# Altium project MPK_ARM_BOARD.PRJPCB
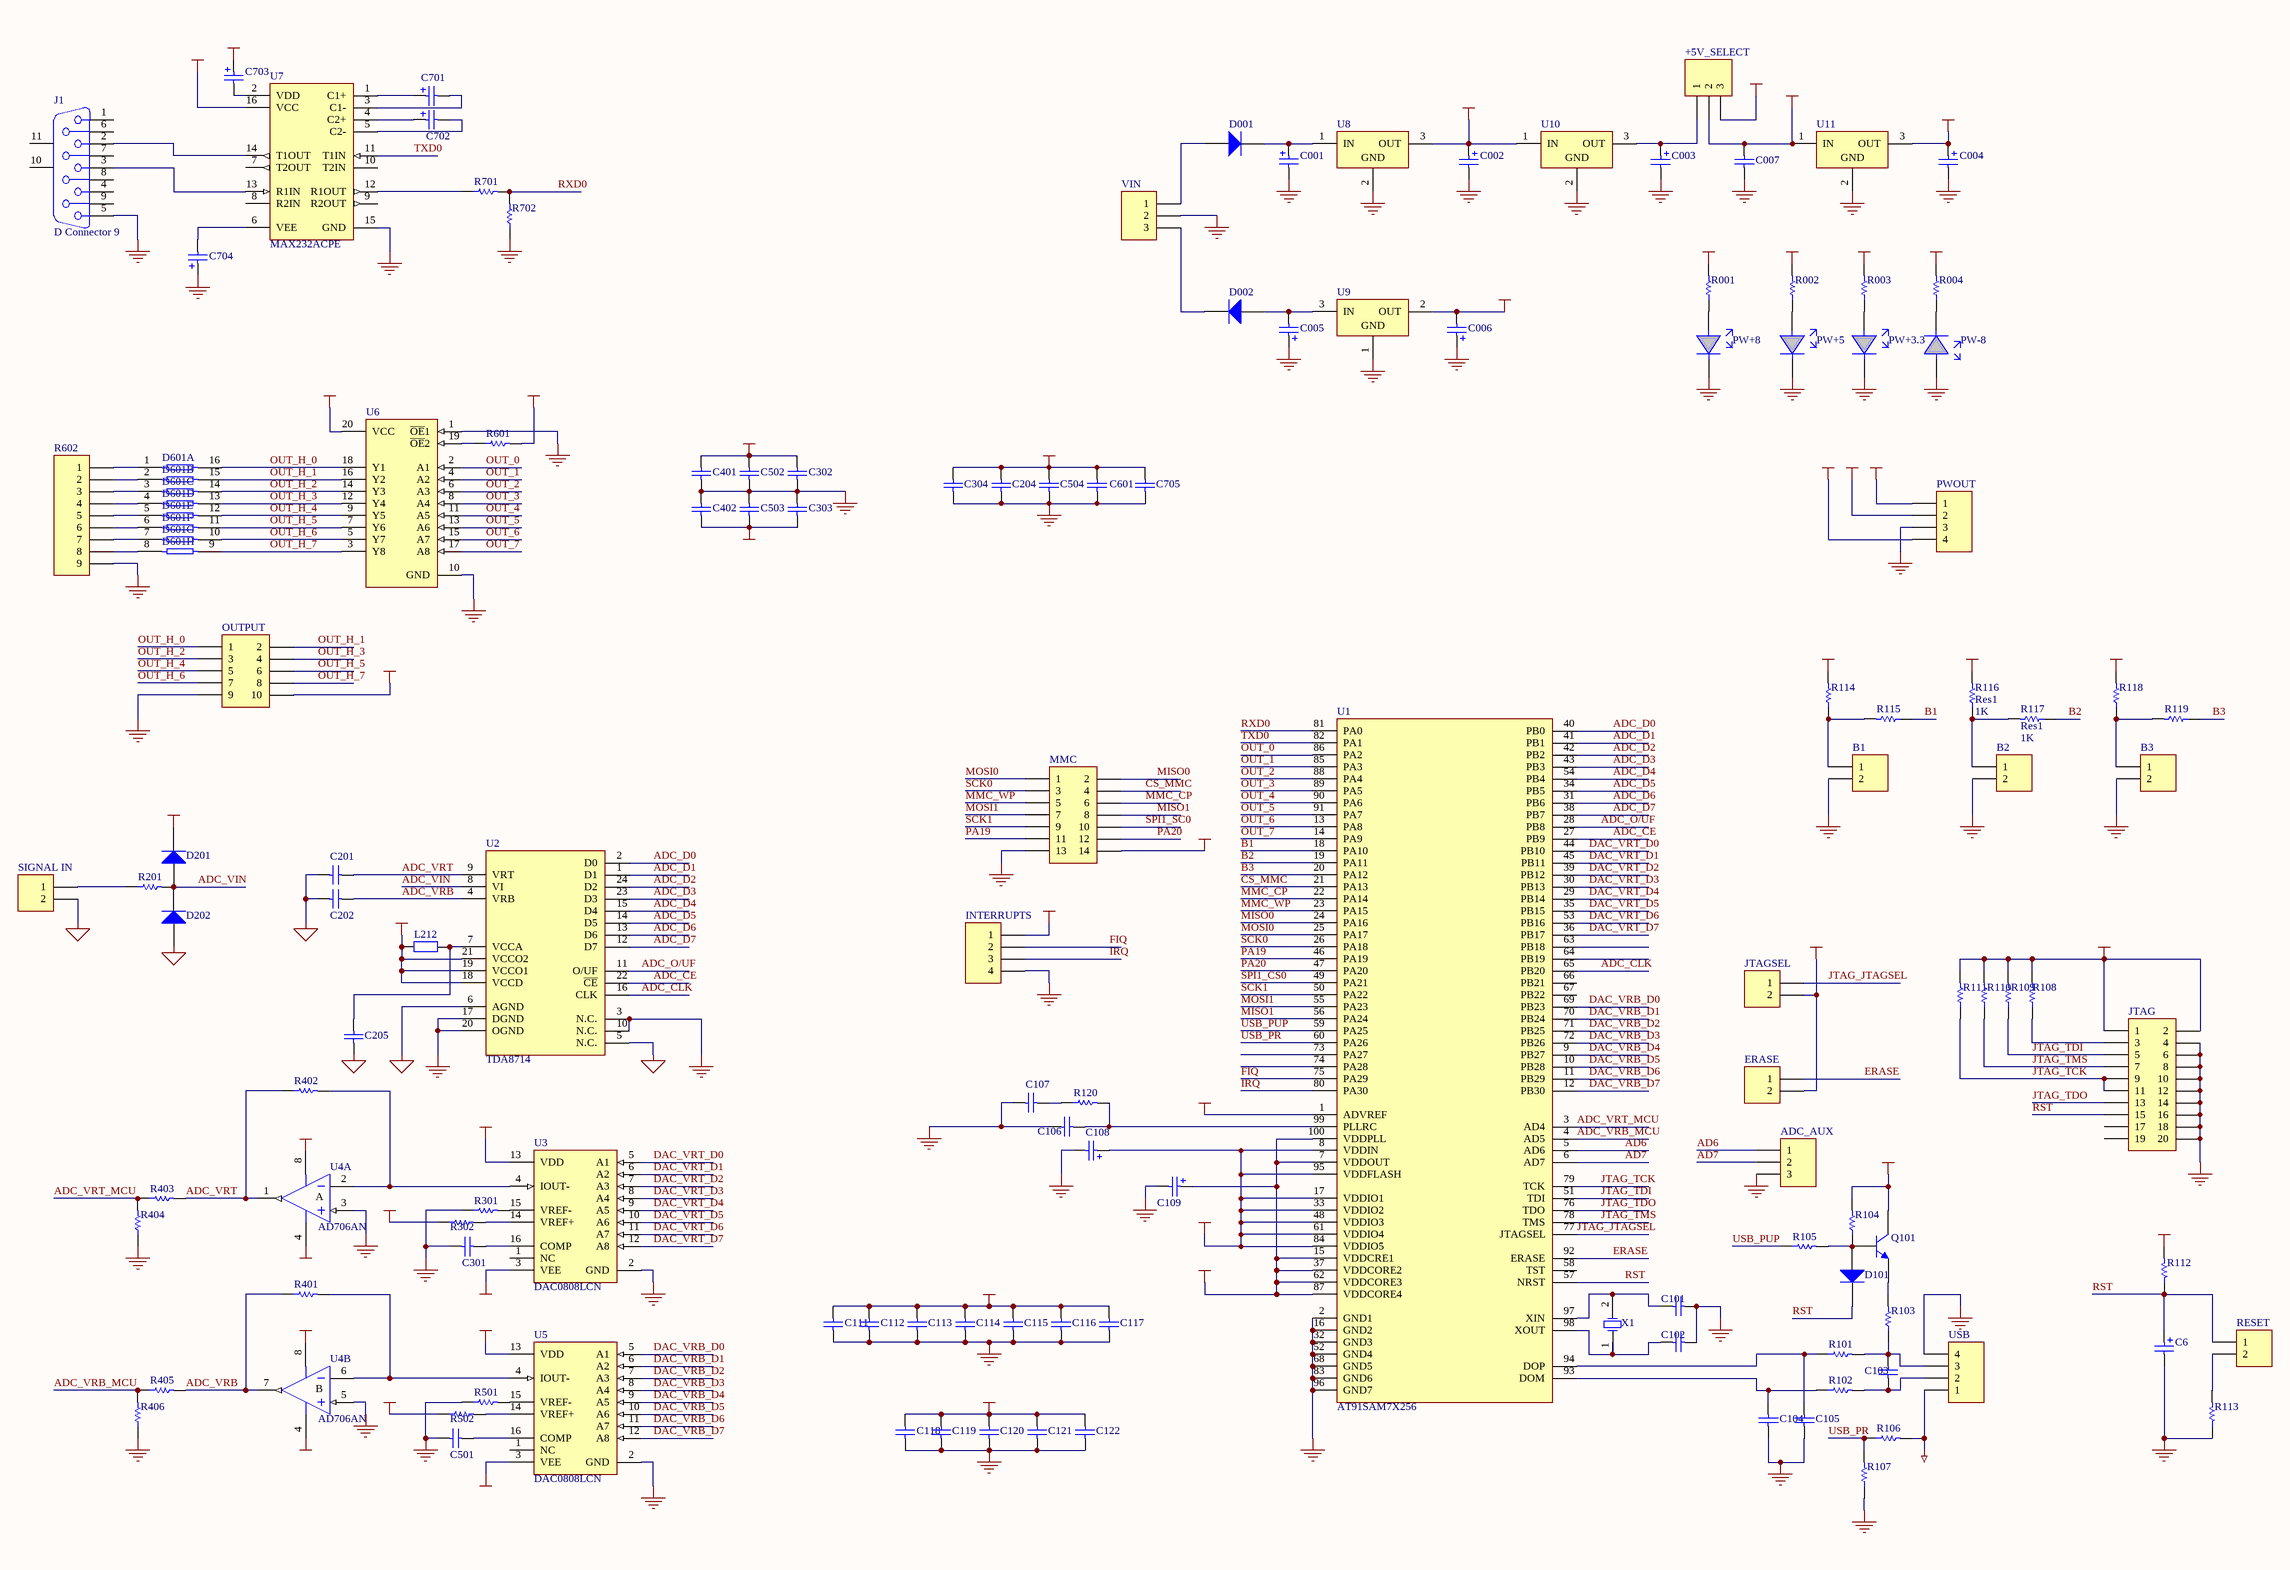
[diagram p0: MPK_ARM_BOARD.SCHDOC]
1 sheet, 129 parts. Net scope: global (net labels, ports and power ports of the same name join across sheets).
Board file: MPK_ARM_BOARD.PCBDOC

## Sheet MPK_ARM_BOARD.SCHDOC
size C

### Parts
+5V_SELECT  Header 3  [HDR1X3]  (value not drawn)
ADC_AUX  Header 3  [HDR1X3]  (value not drawn)
B1  Header 2  [HDR1X2]  (value not drawn)
B2  Header 2  [HDR1X2]  (value not drawn)
B3  Header 2  [HDR1X2]  (value not drawn)
C001  Cap Pol1  [CAPPR5-5X5]  (value not drawn)
C002  Cap Pol1  [CAPPR2-5X6.8]  (value not drawn)
C003  Cap Pol1  [CAPPR2-5X6.8]  (value not drawn)
C004  Cap Pol1  [CAPPR2-5X6.8]  (value not drawn)
C005  Cap Pol1  [CAPPR5-5X5]  (value not drawn)
C6  Cap Pol1  [CAPPR2-5X6.8]  (value not drawn)
C006  Cap Pol1  [CAPPR2-5X6.8]  (value not drawn)
C007  Cap  [CAPR2.54-5.1X3.2]  (value not drawn)
C101  Cap  [CAPR2.54-5.1X3.2]  (value not drawn)
C102  Cap  [CAPR2.54-5.1X3.2]  (value not drawn)
C103  Cap  [CAPR2.54-5.1X3.2]  (value not drawn)
C104  Cap  [CAPR2.54-5.1X3.2]  (value not drawn)
C105  Cap  [CAPR2.54-5.1X3.2]  (value not drawn)
C106  Cap  [CAPR2.54-5.1X3.2]  (value not drawn)
C107  Cap  [CAPR2.54-5.1X3.2]  (value not drawn)
C108  Cap Pol1  [CAPPR2-5X6.8]  (value not drawn)
C109  Cap Pol1  [CAPPR2-5X6.8]  (value not drawn)
C111  Cap  [CAPR2.54-5.1X3.2]  (value not drawn)
C112  Cap  [CAPR2.54-5.1X3.2]  (value not drawn)
C113  Cap  [CAPR2.54-5.1X3.2]  (value not drawn)
C114  Cap  [CAPR2.54-5.1X3.2]  (value not drawn)
C115  Cap  [CAPR2.54-5.1X3.2]  (value not drawn)
C116  Cap  [CAPR2.54-5.1X3.2]  (value not drawn)
C117  Cap  [CAPR2.54-5.1X3.2]  (value not drawn)
C118  Cap  [CAPR2.54-5.1X3.2]  (value not drawn)
C119  Cap  [CAPR2.54-5.1X3.2]  (value not drawn)
C120  Cap  [CAPR2.54-5.1X3.2]  (value not drawn)
C121  Cap  [CAPR2.54-5.1X3.2]  (value not drawn)
C122  Cap  [CAPR2.54-5.1X3.2]  (value not drawn)
C201  Cap  [CAPR2.54-5.1X3.2]  (value not drawn)
C202  Cap  [CAPR2.54-5.1X3.2]  (value not drawn)
C204  Cap  [CAPR2.54-5.1X3.2]  (value not drawn)
C205  Cap  [CAPR2.54-5.1X3.2]  (value not drawn)
C301  Cap  [CAPR2.54-5.1X3.2]  (value not drawn)
C302  Cap  [CAPR2.54-5.1X3.2]  (value not drawn)
C303  Cap  [CAPR2.54-5.1X3.2]  (value not drawn)
C304  Cap  [CAPR2.54-5.1X3.2]  (value not drawn)
C401  Cap  [CAPR2.54-5.1X3.2]  (value not drawn)
C402  Cap  [CAPR2.54-5.1X3.2]  (value not drawn)
C501  Cap  [CAPR2.54-5.1X3.2]  (value not drawn)
C502  Cap  [CAPR2.54-5.1X3.2]  (value not drawn)
C503  Cap  [CAPR2.54-5.1X3.2]  (value not drawn)
C504  Cap  [CAPR2.54-5.1X3.2]  (value not drawn)
C601  Cap  [CAPR2.54-5.1X3.2]  (value not drawn)
C701  Cap Pol1  [CAPPR2-5X6.8]  (value not drawn)
C702  Cap Pol1  [CAPPR2-5X6.8]  (value not drawn)
C703  Cap Pol1  [CAPPR2-5X6.8]  (value not drawn)
C704  Cap Pol1  [CAPPR2-5X6.8]  (value not drawn)
C705  Cap  [CAPR2.54-5.1X3.2]  (value not drawn)
D001  Diode 1N4007  [DIO10.46-5.3x2.8]  (value not drawn)
D002  Diode 1N4007  [DIO10.46-5.3x2.8]  (value not drawn)
D101  Diode 1N4148  [DIO7.1-3.9x1.9]  (value not drawn)
D201  Diode 1N4004  [DIO10.46-5.3x2.8]  (value not drawn)
D202  Diode 1N4004  [DIO10.46-5.3x2.8]  (value not drawn)
D601  Res Pack2  [DIP-16]  (value not drawn)  (parts A,B,C,D,E,F,G,H of 8)
ERASE  Header 2  [HDR1X2]  (value not drawn)
INTERRUPTS  Header 4  [HDR1X4]  (value not drawn)
J1  D Connector 9  [DSUB1.385-2H9]
JTAG  Header 10X2  [HDR2X10]  (value not drawn)
JTAGSEL  Header 2  [HDR1X2]  (value not drawn)
L212  Res2  [AXIAL-0.4]  (value not drawn)
MMC  Header 7X2  [HDR2X7]  (value not drawn)
OUTPUT  Header 5X2  [HDR2X5]  (value not drawn)
PW+3.3  LED  [LED]  (value not drawn)
PW+5  LED  [LED]  (value not drawn)
PW+8  LED  [LED]  (value not drawn)
PW-8  LED  [LED]  (value not drawn)
PWOUT  Header 4  [HDR1X4]  (value not drawn)
Q101  2N3904  [BCY-W3/E4]  (value not drawn)
R001  Res1  [AXIAL-0.3]  (value not drawn)
R002  Res1  [AXIAL-0.3]  (value not drawn)
R003  Res1  [AXIAL-0.3]  (value not drawn)
R004  Res1  [AXIAL-0.3]  (value not drawn)
R101  Res1  [AXIAL-0.3]  (value not drawn)
R102  Res1  [AXIAL-0.3]  (value not drawn)
R103  Res1  [AXIAL-0.3]  (value not drawn)
R104  Res1  [AXIAL-0.3]  (value not drawn)
R105  Res1  [AXIAL-0.3]  (value not drawn)
R106  Res1  [AXIAL-0.3]  (value not drawn)
R107  Res1  [AXIAL-0.3]  (value not drawn)
R108  Res1  [AXIAL-0.3]  (value not drawn)
R109  Res1  [AXIAL-0.3]  (value not drawn)
R110  Res1  [AXIAL-0.3]  (value not drawn)
R111  Res1  [AXIAL-0.3]  (value not drawn)
R112  Res1  [AXIAL-0.3]  (value not drawn)
R113  Res1  [AXIAL-0.3]  (value not drawn)
R114  Res1  [AXIAL-0.3]  (value not drawn)
R115  Res1  [AXIAL-0.3]  (value not drawn)
R116  Res1  value 1K  [AXIAL-0.3]
R117  Res1  value 1K  [AXIAL-0.3]
R118  Res1  [AXIAL-0.3]  (value not drawn)
R119  Res1  [AXIAL-0.3]  (value not drawn)
R120  Res1  [AXIAL-0.3]  (value not drawn)
R201  Res1  [AXIAL-0.3]  (value not drawn)
R301  Res1  [AXIAL-0.3]  (value not drawn)
R302  Res1  [AXIAL-0.3]  (value not drawn)
R401  Res1  [AXIAL-0.3]  (value not drawn)
R402  Res1  [AXIAL-0.3]  (value not drawn)
R403  Res1  [AXIAL-0.3]  (value not drawn)
R404  Res1  [AXIAL-0.3]  (value not drawn)
R405  Res1  [AXIAL-0.3]  (value not drawn)
R406  Res1  [AXIAL-0.3]  (value not drawn)
R501  Res1  [AXIAL-0.3]  (value not drawn)
R502  Res1  [AXIAL-0.3]  (value not drawn)
R601  Res1  [AXIAL-0.3]  (value not drawn)
R602  Header 9  [HDR1X9]  (value not drawn)
R701  Res1  [AXIAL-0.3]  (value not drawn)
R702  Res1  [AXIAL-0.3]  (value not drawn)
RESET  Header 2  [HDR1X2]  (value not drawn)
SIGNAL_IN  Header 2  [HDR1X2]  (value not drawn)
U1  AT91SAM7X256  [LQFP100]
U2  TDA8714  [SOP24]
U3  DAC0808LCN  [N16A]
U4  AD706AN  [N-8_A]  (parts A,B of 2)
U5  DAC0808LCN  [N16A]
U6  SN74HC244N  [N020]  (value not drawn)
U7  MAX232ACPE  [PE16A]
U8  MC78M08BT  [221A-04]  (value not drawn)
U9  L7908ACV  [TO220V]  (value not drawn)
U10  MC7805ACT  [221A-04]  (value not drawn)
U11  LM340T-18  [221A-04]  (value not drawn)
USB  Header 4  [HDR1X4]  (value not drawn)
VIN  Header 3  [HDR1X3]  (value not drawn)
X1  ECS-10-13-1  [HC-49U]  (value not drawn)

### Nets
+1.8V: C109.1 C118.2 C119.2 C120.2 C121.2 C122.2 U1.7(VDDOUT) U1.15(VDDCRE1) U1.37(VDDCORE2) U1.62(VDDCORE3) U1.87(VDDCORE4) U1.100(VDDPLL)
+3.3V: C004.1 C108.1 C111.2 C112.2 C113.2 C114.2 C115.2 C116.2 C117.2 ERASE.2 INTERRUPTS.1 JTAG.1 JTAG.2 JTAGSEL.2 MMC.14 Q101.3(C) R003.2 R104.2 R108.2 R109.2 R110.2 R111.2 R112.2 R114.2 R116.2 R118.2 U1.1(ADVREF) U1.8(VDDIN) U1.17(VDDIO1) U1.33(VDDIO2) U1.48(VDDIO3) U1.61(VDDIO4) U1.84(VDDIO5) U1.95(VDDFLASH) U11.3(OUT)
+5V: +5V_SELECT.2 C007.2 C204.2 C304.2 C504.2 C601.2 C703.1 C705.2 D201.2(K) L212.1 OUTPUT.10 PWOUT.2 R002.2 R302.1 R502.1 R601.2 U2.18(VCCD) U2.19(VCCO1) U2.21(VCCO2) U6.20(VCC) U7.16(VCC) U11.1(IN)
+5V_USB: +5V_SELECT.3 R106.2 USB.1
+8V: C002.1 C302.2 C401.2 C502.2 PWOUT.1 R001.2 U3.13(VDD) U4.8(V+) U5.13(VDD) U8.3(OUT) U10.1(IN)
-8V: C006.2 C303.1 C402.1 C503.1 PWOUT.4 R004.2 U3.3(VEE) U4.4(V-) U5.3(VEE) U9.2(OUT)
AGND: C201.1 C202.1 C205.1 D202.1(A) SIGNAL_IN.2 U2.5(N.C.) U2.6(AGND)
GND: ADC_AUX.3 B1.2 B2.2 B3.2 C001.2 C002.2 C003.2 C004.2 C005.1 C006.1 C6.2 C007.1 C101.2 C102.2 C104.1 C105.1 C106.1 C107.1 C108.2 C109.2 C111.1 C112.1 C113.1 C114.1 C115.1 C116.1 C117.1 C118.1 C119.1 C120.1 C121.1 C122.1 C204.1 C301.1 C302.1 C303.2 C304.1 C401.1 C402.2 C501.1 C502.1 C503.2 C504.1 C601.1 C704.1 C705.1 INTERRUPTS.4 J1.5 JTAG.4 JTAG.6 JTAG.8 JTAG.10 JTAG.12 JTAG.14 JTAG.16 JTAG.18 JTAG.20 MMC.13 OUTPUT.9 PW+3.3.2 PW+5.2 PW+8.2 PW-8.1 PWOUT.3 R107.1 R113.1 R301.1 R404.1 R406.1 R501.1 R602.9 R702.1 U1.2(GND1) U1.16(GND2) U1.32(GND3) U1.52(GND4) U1.68(GND5) U1.83(GND6) U1.96(GND7) U2.3(N.C.) U2.10(N.C.) U2.17(DGND) U2.20(OGND) U3.2(GND) U4.3(IN+) U4.5(IN+) U5.2(GND) U6.1(~{OE}1) U6.10(GND) U7.15(GND) U8.2(GND) U9.1(GND) U10.2(GND) U11.2(GND) USB.4 VIN.2
AD6: ADC_AUX.1 U1.5(AD6)
AD7: ADC_AUX.2 U1.6(AD7)
ADC_CE: U1.27(PB9) U2.22(~{CE})
ADC_CLK: U1.65(PB20) U2.16(CLK)
ADC_D0: U1.40(PB0) U2.2(D0)
ADC_D1: U1.41(PB1) U2.1(D1)
ADC_D2: U1.42(PB2) U2.24(D2)
ADC_D3: U1.43(PB3) U2.23(D3)
ADC_D4: U1.54(PB4) U2.15(D4)
ADC_D5: U1.34(PB5) U2.14(D5)
ADC_D6: U1.31(PB6) U2.13(D6)
ADC_D7: U1.38(PB7) U2.12(D7)
ADC_O/UF: U1.28(PB8) U2.11(O/UF)
ADC_VIN: D201.1(A) D202.2(K) R201.2 U2.8(VI)
ADC_VRB: C202.2 R401.1 R405.2 U2.4(VRB) U4.7(OUT)
ADC_VRB_MCU: R405.1 R406.2 U1.4(AD5)
ADC_VRT: C201.2 R402.1 R403.2 U2.9(VRT) U4.1(OUT)
ADC_VRT_MCU: R403.1 R404.2 U1.3(AD4)
B1: R115.1 U1.18(PA10)
B2: R117.1 U1.19(PA11)
B3: R119.1 U1.20(PA12)
CS_MMC: MMC.4 U1.21(PA13)
DAC_VRB_D0: U1.69(PB23) U5.5(A1)
DAC_VRB_D1: U1.70(PB24) U5.6(A2)
DAC_VRB_D2: U1.71(PB25) U5.7(A3)
DAC_VRB_D3: U1.72(PB26) U5.8(A4)
DAC_VRB_D4: U1.9(PB27) U5.9(A5)
DAC_VRB_D5: U1.10(PB28) U5.10(A6)
DAC_VRB_D6: U1.11(PB29) U5.11(A7)
DAC_VRB_D7: U1.12(PB30) U5.12(A8)
DAC_VRT_D0: U1.44(PB10) U3.5(A1)
DAC_VRT_D1: U1.45(PB11) U3.6(A2)
DAC_VRT_D2: U1.39(PB12) U3.7(A3)
DAC_VRT_D3: U1.30(PB13) U3.8(A4)
DAC_VRT_D4: U1.29(PB14) U3.9(A5)
DAC_VRT_D5: U1.35(PB15) U3.10(A6)
DAC_VRT_D6: U1.53(PB16) U3.11(A7)
DAC_VRT_D7: U1.36(PB17) U3.12(A8)
ERASE: ERASE.1 U1.92(ERASE)
FIQ: INTERRUPTS.2 U1.75(PA29)
IRQ: INTERRUPTS.3 U1.80(PA30)
JTAG_JTAGSEL: JTAGSEL.1 U1.77(JTAGSEL)
JTAG_TCK: JTAG.9 JTAG.11 R111.1 U1.79(TCK)
JTAG_TDI: JTAG.5 R109.1 U1.51(TDI)
JTAG_TDO: JTAG.13 U1.76(TDO)
JTAG_TMS: JTAG.7 R110.1 U1.78(TMS)
MISO0: MMC.2 U1.24(PA16)
MISO1: MMC.8 U1.56(PA24)
MMC_CP: MMC.6 U1.22(PA14)
MMC_WP: MMC.5 U1.23(PA15)
MOSI0: MMC.1 U1.25(PA17)
MOSI1: MMC.7 U1.55(PA23)
OUT_0: U1.86(PA2) U6.2(A1)
OUT_1: U1.85(PA3) U6.4(A2)
OUT_2: U1.88(PA4) U6.6(A3)
OUT_3: U1.89(PA5) U6.8(A4)
OUT_4: U1.90(PA6) U6.11(A5)
OUT_5: U1.91(PA7) U6.13(A6)
OUT_6: U1.13(PA8) U6.15(A7)
OUT_7: U1.14(PA9) U6.17(A8)
OUT_H_0: D601.16 OUTPUT.1 U6.18(Y1)
OUT_H_1: D601.15 OUTPUT.2 U6.16(Y2)
OUT_H_2: D601.14 OUTPUT.3 U6.14(Y3)
OUT_H_3: D601.13 OUTPUT.4 U6.12(Y4)
OUT_H_4: D601.12 OUTPUT.5 U6.9(Y5)
OUT_H_5: D601.11 OUTPUT.6 U6.7(Y6)
OUT_H_6: D601.10 OUTPUT.7 U6.5(Y7)
OUT_H_7: D601.9 OUTPUT.8 U6.3(Y8)
PA19: MMC.11 U1.46(PA19)
PA20: MMC.12 U1.47(PA20)
RST: C6.1 D101.2(K) JTAG.15 R112.1 RESET.1 U1.57(NRST)
RXD0: R701.2 R702.2 U1.81(PA0)
SCK0: MMC.3 U1.26(PA18)
SCK1: MMC.9 U1.50(PA22)
SPI1_CS0: U1.49(PA21)
SPI1_SC0: MMC.10
TXD0: U1.82(PA1) U7.11(T1IN)
USB_PR: R106.1 R107.2 U1.60(PA26)
USB_PUP: R105.1 U1.59(PA25)
Net+5V_SELECT_1: +5V_SELECT.1 C003.1 U10.3(OUT)
NetB1_1: B1.1 R114.1 R115.2
NetB2_1: B2.1 R116.1 R117.2
NetB3_1: B3.1 R118.1 R119.2
NetC001_1: C001.1 D001.2(K) U8.1(IN)
NetC005_2: C005.2 D002.1(A) U9.3(IN)
NetC101_1: C101.1 U1.97(XIN) X1.2(OSC2)
NetC102_1: C102.1 U1.98(XOUT) X1.1(OSC1)
NetC103_1: C103.1 R102.2 USB.2
NetC103_2: C103.2 R101.2 R103.1 USB.3
NetC104_2: C104.2 R102.1 U1.93(DOM)
NetC105_2: C105.2 R101.1 U1.94(DOP)
NetC106_2: C106.2 R120.2 U1.99(PLLRC)
NetC107_2: C107.2 R120.1
NetC205_2: C205.2 L212.2 U2.7(VCCA)
NetC301_2: C301.2 U3.16(COMP)
NetC501_2: C501.2 U5.16(COMP)
NetC701_1: C701.1 U7.1(C1+)
NetC701_2: C701.2 U7.3(C1-)
NetC702_1: C702.1 U7.4(C2+)
NetC702_2: C702.2 U7.5(C2-)
NetC703_2: C703.2 U7.2(VDD)
NetC704_2: C704.2 U7.6(VEE)
NetD001_1: D001.1(A) VIN.1
NetD002_2: D002.2(K) VIN.3
NetD101_1: D101.1(A) Q101.2(B) R104.1 R105.2
NetD601_1: D601.1 R602.1
NetD601_2: D601.2 R602.2
NetD601_3: D601.3 R602.3
NetD601_4: D601.4 R602.4
NetD601_5: D601.5 R602.5
NetD601_6: D601.6 R602.6
NetD601_7: D601.7 R602.7
NetD601_8: D601.8 R602.8
NetJ1_2: J1.2 U7.14(T1OUT)
NetJ1_3: J1.3 U7.13(R1IN)
NetJTAG_3: JTAG.3 R108.1
NetPW+3.3_1: PW+3.3.1 R003.1
NetPW+5_1: PW+5.1 R002.1
NetPW+8_1: PW+8.1 R001.1
NetPW-8_2: PW-8.2 R004.1
NetQ101_1: Q101.1(E) R103.2
NetR113_2: R113.2 RESET.2
NetR201_1: R201.1 SIGNAL_IN.1
NetR301_2: R301.2 U3.15(VREF-)
NetR302_2: R302.2 U3.14(VREF+)
NetR401_2: R401.2 U4.6(IN-) U5.4(IOUT-)
NetR402_2: R402.2 U3.4(IOUT-) U4.2(IN-)
NetR501_2: R501.2 U5.15(VREF-)
NetR502_2: R502.2 U5.14(VREF+)
NetR601_1: R601.1 U6.19(~{OE}2)
NetR701_1: R701.1 U7.12(R1OUT)

Not connected (* = marked no-connect by the designer): J1 1 4 6 7 8 9 10(MH1) 11(MH2); JTAG 17 19; U1 58(TST) 63(PB18) 64(PB19) 66(PB21) 67(PB22) 73(PA27) 74(PA28); U3 1(NC); U5 1(NC); U7 7(T2OUT) 8(R2IN) 9(R2OUT) 10(T2IN)

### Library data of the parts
+5V_SELECT ADC_AUX VIN = Header 3: Header, 3-Pin
B1-B3 ERASE JTAGSEL RESET SIGNAL_IN = Header 2: Header, 2-Pin
C001 C002 C003 C004 C005 C6 C006 C108 C109 C701-C704 = Cap Pol1: Polarized Capacitor (Radial); Value: 100pF
C007 C101-C107 C111-C122 C201 C202 C204 C205 C301-C304 C401 C402 C501-C504 C601 C705 = Cap: Capacitor; Value: 100pF
D001 D002 = Diode 1N4007: 1 Amp General Purpose Rectifier; Revision 1: 11-Jul-2000: SIM Model Added.; Revision 2: 17-Jul-2002: Re-released for DXP Platform.; Package Information: Latest Revision: Aug-1999; Code - JEDEC: DO-204-AL
D101 = Diode 1N4148: High Conductance Fast Diode; Revision 1: 11-Jul-2000: SIM Model Added.; Revision 2: 17-Jul-2002: Re-released for DXP Platform.; Code - JEDEC: DO-204-AH
D201 D202 = Diode 1N4004: 1 Amp General Purpose Rectifier; Revision 1: 11-Jul-2000: SIM Model Added.; Revision 2: 17-Jul-2002: Re-released for DXP Platform.; Package Information: Latest Revision: Aug-1999; Code - JEDEC: DO-204-AL
D601 = Res Pack2: Resistor Array - Parts; Code - JEDEC: MO-001-AC; Value: 1K
INTERRUPTS PWOUT USB = Header 4: Header, 4-Pin
J1 = D Connector 9: Receptacle Assembly, 9 Position, Right Angle; Package Information: Latest Revision: O; Positions: 9
JTAG = Header 10X2: Header, 10-Pin, Dual row
L212 = Res2: Resistor; Value: 1K
MMC = Header 7X2: Header, 7-Pin, Dual row
OUTPUT = Header 5X2: Header, 5-Pin, Dual row
Q101 = 2N3904: NPN General Purpose Amplifier; Revision 1: 11-Jul-2000: SIM Model Added.; Revision 2: 17-Jul-2002: Re-released for DXP Platform.; Revision 3: 15-Jan-2003: PCB Footprint 'BCY-W3/D4.7' replaced; Code - JEDEC: TO-92A
R001 R002 R003 R004 R101-R115 R118-R120 R201 R403-R406 R601 R701 R702 = Res1: Resistor; Value: 1K
R116 R117 = Res1: Resistor
R301 R302 R402 R501 R502 = Res1: Resistor; Value: 5.00k
R401 = Res1: Resistor; Value: 5.00K
R602 = Header 9: Header, 9-Pin
U1 = AT91SAM7X512/256/128: Atmel ARM Core 32 Microcontroller
U3 U5 = DAC0808LCN: 8-Bit D/A Converter; Package Information: Latest Revision: 2000
U4 = AD706AN: Dual Picoampere Input Current Bipolar Operational Amplifier; Revision 1: 10-Jul-2000: SIM Model Added.; Revision 2: 17-Jul-2002: Re-released for DXP Platform.; Code - JEDEC: MO-001-AN
U6 = SN74HC244N: Octal Buffer and Line Driver with 3-State Outputs; Package Information: Latest Revision: Oct-1995
U7 = MAX232ACPE: +5V Powered, Multi-Channel RS-232 Driver/Receiver; Package Information: Latest Revision: 1997; Code - JEDEC: MS-001-BB
U8 = MC78M08BT: 3-Terminal Medium-Current Positive Fixed Voltage Regulator; Note: Pin 2 is electrically connected to TAB; Code - JEDEC: TO-262-AA
U9 = L7908ACV: 2% Negative Voltage Regulator; Note: Tab is connected to pin 3 (IN).
U10 = MC7805ACT: 3-Terminal Positive Fixed Voltage Regulator; Note: Pin 2 is electrically connected to TAB; Code - JEDEC: TO-262-AA
U11 = LM340T-18: 3-Terminal Positive Fixed Voltage Regulator; Note: Heatsink surface connected to pin 2.; Code - JEDEC: TO-262-AA
X1 = ECS-10-13-1: Crystal Oscillator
